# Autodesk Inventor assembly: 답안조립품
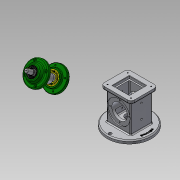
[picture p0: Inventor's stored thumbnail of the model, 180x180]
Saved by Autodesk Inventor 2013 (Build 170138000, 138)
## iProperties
Created: 2019-08
Part Number: 답안조립품
Document SubType Name: Assembly
Designer: default
Author: default
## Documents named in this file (8)
- C:\Users\default.default-PC\Desktop\490804V1015\답안조립품.iam
- C:\Users\default.default-PC\Desktop\490804V1015\본체.ipt
- C:\Users\default.default-PC\Desktop\490804V1015\베어링 17 x 40 x 12.ipt
- C:\Users\default.default-PC\Desktop\490804V1015\편심축.ipt
- C:\Users\default.default-PC\Desktop\490804V1015\뒤커버.ipt
- C:\Users\default.default-PC\Desktop\490804V1015\앞커버.ipt
- C:\Users\default.default-PC\Desktop\490804V1015\키 4 x 4 x 12.ipt
- C:\Users\default.default-PC\Desktop\490804V1015\오일 실 17 30 8.ipt
